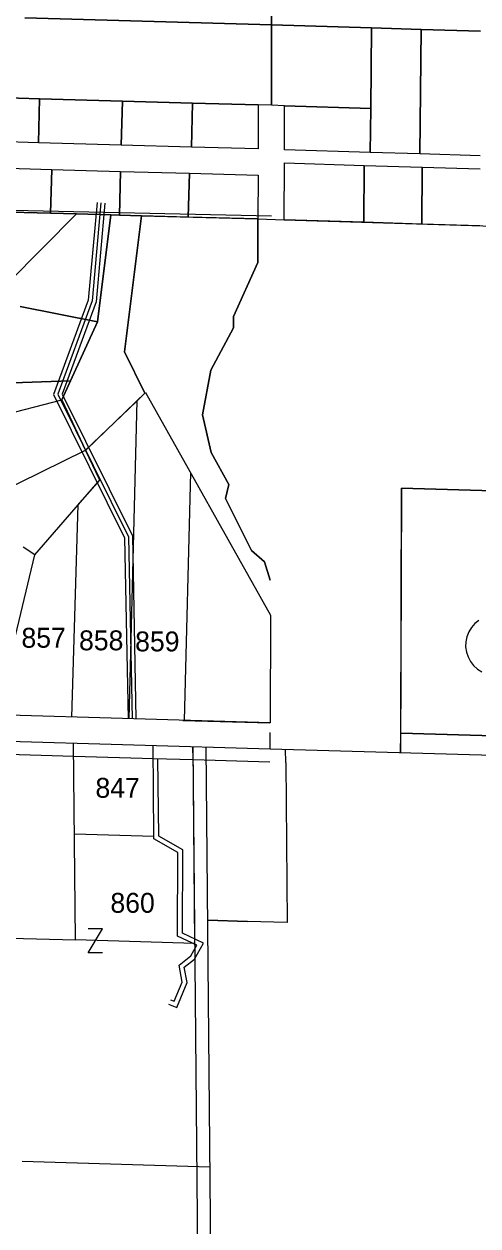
# Model space of a CAD drawing. Extents: x 582596 to 627039, y 145946 to 197316.
# Drawn here: x 619859 to 621001, y 163403 to 166425 of the extents above; entities that cross this region are included whole.
import ezdxf

# ---------------------------------------------------------------- set-up
doc = ezdxf.new("R2010")
doc.units = 0
for name, color, linetype in [('Defpoints 2', 7, 'Continuous'), ('E_RW_EasementUtility', 7, 'Continuous'), ('E_RW_Existing', 7, 'Continuous'), ('E_RW_SixteenthLine', 7, 'Continuous'), ('P_RW_MinorLotLine', 7, 'Continuous'), ('P_RW_PropertyConnector', 7, 'Continuous'), ('P_RW_PropertyLine', 7, 'Continuous'), ('P_RW_SectionLine', 7, 'Continuous')]:
    doc.layers.add(name, color=color, linetype=linetype)

msp = doc.modelspace()

# ---------------------------------------------------------------- linework, layer by layer
at = {"layer": 'E_RW_EasementUtility'}
msp.add_line((620317, 164607.9), (620340.4, 162042.5), dxfattribs=at)
for points in [[(620043.1, 165976.9), (620021, 165731.2), (619933.5, 165493.8), (620112.5, 165133.7), (620121, 164678.5)], [(620053, 165976), (620030.8, 165729), (619944.4, 165494.4), (620122.4, 165136.2), (620131, 164678.3)], [(620063, 165975.1), (620040.6, 165726.7), (619955.2, 165495), (620132.4, 165138.6), (620141, 164678)], [(620223.1, 163961.1), (620243.4, 163952.6), (620269.6, 164015.4), (620262.3, 164054), (620287.9, 164074.2), (620310.6, 164114.4), (620257.7, 164139.6), (620258.6, 164349.4), (620198.1, 164383.6), (620196.3, 164578.3)], [(620227.7, 163972.1), (620236.9, 163968.3), (620257.2, 164016.7), (620249.2, 164058.9), (620278.6, 164082.2), (620293.9, 164109.1), (620245.7, 164132.1), (620246.6, 164342.4), (620186.2, 164376.5), (620186.1, 164383.7)]]:
    msp.add_lwpolyline(points, dxfattribs=at)
at = {"layer": 'E_RW_Existing'}
for p, q in [((619575.4, 164596.3), (619984.8, 164584.4)), ((619984.8, 164584.4), (620184.7, 164578.7)), ((620284.6, 164575.8), (620477.6, 164570.2))]:
    msp.add_line(p, q, dxfattribs=at)
at = {"layer": 'E_RW_SixteenthLine'}
msp.add_line((617844.3, 166000.7), (620481.9, 165942.8), dxfattribs=at)
at = {"layer": 'P_RW_MinorLotLine'}
msp.add_line((620288.5, 164113.8), (619988.6, 164122.5), dxfattribs=at)
at = {"layer": 'P_RW_PropertyConnector'}
for p, q in [((620020.8, 164090.3), (620056.5, 164150.2)), ((620056.5, 164150.2), (620020.9, 164150.2)), ((620038.7, 164120.2), (620038.7, 164120.2)), ((620056.5, 164090.3), (620020.8, 164090.3))]:
    msp.add_line(p, q, dxfattribs=at)
at = {"layer": 'P_RW_PropertyLine'}
for p, q in [((620483.6, 167042.3), (620482, 166423.4)), ((620482, 166423.4), (620483.6, 167042.3)), ((619861.4, 166440.5), (620482, 166423.3)), ((620482, 166423.3), (619861.4, 166440.5)), ((620482, 166423.3), (620481.5, 166221.1)), ((620481.5, 166221.1), (620482, 166423.3)), ((620482, 166423.4), (620482, 166423.3)), ((620733.3, 166415.5), (620482, 166423.4)), ((620482, 166423.3), (620482, 166423.4)), ((620482, 166423.4), (620733.3, 166415.5)), ((620733.3, 166415.5), (620731.3, 166213.3)), ((620731.3, 166213.3), (620733.3, 166415.5)), ((620858.3, 166411.6), (620733.3, 166415.5)), ((620733.3, 166415.5), (620858.3, 166411.6)), ((620858.3, 166411.6), (620855.1, 166098.7)), ((620855.1, 166098.7), (620858.3, 166411.6)), ((621007.6, 166407), (620858.3, 166411.6)), ((620858.3, 166411.6), (621007.6, 166407)), ((619743.6, 166241.6), (619898.6, 166237.3)), ((619898.6, 166237.3), (619743.6, 166241.6)), ((619898.6, 166237.3), (619895.5, 166126.6)), ((619895.5, 166126.6), (619898.6, 166237.3)), ((619898.6, 166237.3), (620107.1, 166231.5)), ((620107.1, 166231.5), (619898.6, 166237.3)), ((620104.1, 166120.9), (620107.1, 166231.5)), ((620107.1, 166231.5), (620104.1, 166120.9)), ((620107.1, 166231.5), (620283.4, 166226.6)), ((620283.4, 166226.6), (620107.1, 166231.5)), ((620283.4, 166226.6), (620280.4, 166116)), ((620280.4, 166116), (620283.4, 166226.6)), ((620283.4, 166226.6), (620448.5, 166222)), ((620448.5, 166222), (620283.4, 166226.6)), ((620448.5, 166222), (620448.2, 166111.3)), ((620481.5, 166221.1), (620448.5, 166222)), ((620514.5, 166220), (620481.5, 166221.1)), ((620514.2, 166109.3), (620514.5, 166220)), ((620731.3, 166213.3), (620514.5, 166220)), ((620514.5, 166220), (620731.3, 166213.3)), ((620731.3, 166213.3), (620730.1, 166102.6)), ((620730.1, 166102.6), (620731.3, 166213.3)), ((619895.5, 166126.6), (619740.5, 166131)), ((620104.1, 166120.9), (619895.5, 166126.6)), ((620280.4, 166116), (620104.1, 166120.9)), ((620448.2, 166111.3), (620280.4, 166116)), ((620730.1, 166102.6), (620514.2, 166109.3)), ((620855.1, 166098.7), (620730.1, 166102.6)), ((621006.5, 166094), (620855.1, 166098.7)), ((619756.6, 166064.5), (619929.4, 166059.7)), ((619929.4, 166059.7), (619926.3, 165949.7)), ((619926.3, 165949.7), (619929.4, 166059.7)), ((619929.4, 166059.7), (620102.2, 166054.9)), ((620102.2, 166054.9), (620099.2, 165944.9)), ((620099.2, 165944.9), (620102.2, 166054.9)), ((620102.2, 166054.9), (620275.4, 166050.1)), ((620513.8, 165933.3), (620514.1, 166076.3)), ((620514.1, 166076.3), (620714.5, 166070)), ((620714.5, 166070), (620714, 165927.1)), ((620714, 165927.1), (620714.5, 166070)), ((620714.5, 166070), (620860.5, 166065.5)), ((620860.5, 166065.5), (620859.9, 165922.5)), ((620859.9, 165922.5), (620860.5, 166065.5)), ((620860.5, 166065.5), (621006.4, 166060.9)), ((620275.4, 166050.1), (620272.3, 165940.1)), ((620272.3, 165940.1), (620275.4, 166050.1)), ((620275.4, 166050.1), (620448.1, 166045.3)), ((620448.1, 166045.3), (620447.8, 165935.2)), ((619926.3, 165949.7), (619753.5, 165954.5)), ((619753.5, 165954.5), (619926.3, 165949.7)), ((619820.5, 165775.4), (619991.2, 165947.9)), ((619991.2, 165947.9), (619820.5, 165775.4)), ((619991.2, 165947.9), (619926.3, 165949.7)), ((619926.3, 165949.7), (619991.2, 165947.9)), ((620077.9, 165945.5), (619991.2, 165947.9)), ((619991.2, 165947.9), (620077.9, 165945.5)), ((620077.9, 165945.5), (620044.1, 165676.2)), ((620044.1, 165676.2), (620077.9, 165945.5)), ((620099.2, 165944.9), (620077.9, 165945.5)), ((620077.9, 165945.5), (620099.2, 165944.9)), ((620155, 165943.4), (620099.2, 165944.9)), ((620099.2, 165944.9), (620155, 165943.4)), ((620112.2, 165601.2), (620155, 165943.4)), ((620155, 165943.4), (620112.2, 165601.2)), ((620155, 165943.4), (620447.8, 165935.2)), ((620272.3, 165940.1), (620155, 165943.4)), ((620447.8, 165935.2), (620272.3, 165940.1)), ((620447.8, 165935.2), (620447.5, 165826.1)), ((620447.5, 165826.1), (620447.8, 165935.2)), ((620447.8, 165935.2), (620513.8, 165933.3)), ((620714, 165927.1), (620513.8, 165933.3)), ((620513.8, 165933.3), (621140.8, 165913.7)), ((620859.9, 165922.5), (620714, 165927.1)), ((621005.9, 165918), (620859.9, 165922.5)), ((620447.5, 165826.1), (620386.2, 165690.3)), ((620386.2, 165690.3), (620447.5, 165826.1)), ((619849.4, 165715.3), (620044.1, 165676.2)), ((620044.1, 165676.2), (619849.4, 165715.3)), ((620044.1, 165676.2), (619976.2, 165528)), ((619976.2, 165528), (620044.1, 165676.2)), ((620386.1, 165661.2), (620329, 165554.7)), ((620329, 165554.7), (620386.1, 165661.2)), ((620386.2, 165690.3), (620386.1, 165661.2)), ((620386.1, 165661.2), (620386.2, 165690.3)), ((620163.6, 165497.3), (620112.2, 165601.2)), ((620112.2, 165601.2), (620163.6, 165497.3)), ((620329, 165554.7), (620308.5, 165443)), ((620308.5, 165443), (620329, 165554.7)), ((619976.2, 165528), (619807, 165522.5)), ((619807, 165522.5), (619976.2, 165528)), ((619954.6, 165480.7), (619976.2, 165528)), ((619976.2, 165528), (619954.6, 165480.7)), ((619669.6, 165407), (619954.6, 165480.7)), ((619954.6, 165480.7), (620014.3, 165353.9)), ((620014.3, 165353.9), (619954.6, 165480.7)), ((620015.6, 165355.1), (620164.9, 165498.6)), ((620141.9, 165476.5), (620163.6, 165497.3)), ((620163.6, 165497.3), (620141.9, 165476.5)), ((620164.9, 165498.6), (620479.5, 164939.2)), ((620014.3, 165353.9), (620141.9, 165476.5)), ((620141.9, 165476.5), (620014.3, 165353.9)), ((620143.1, 165477.7), (620122.9, 164678.5)), ((620308.5, 165443), (620330.3, 165348)), ((620330.3, 165348), (620308.5, 165443)), ((619776.8, 165236.9), (620014.3, 165353.9)), ((620049.7, 165278.8), (620014.3, 165353.9)), ((620014.3, 165353.9), (620049.7, 165278.8)), ((620330.3, 165348), (620374.4, 165267.7)), ((620374.4, 165267.7), (620330.3, 165348)), ((619886.6, 165090.9), (620050.9, 165280)), ((619994.3, 165215), (620049.7, 165278.8)), ((620278, 165297.5), (620262.2, 164674.5)), ((620374.4, 165267.7), (620366.4, 165232.6)), ((620366.4, 165232.6), (620374.4, 165267.7)), ((620808.9, 165258.2), (620806.5, 164592.4)), ((620806.7, 164642.4), (620808.9, 165258.2)), ((621138.8, 165248.3), (620808.9, 165258.2)), ((620808.9, 165258.2), (621138.8, 165248.3)), ((619980.1, 164682.6), (619995.5, 165216.3)), ((620366.4, 165232.6), (620431.7, 165101.7)), ((620431.7, 165101.7), (620366.4, 165232.6)), ((619837.8, 164886.7), (619886.6, 165090.9)), ((619886.6, 165090.9), (619857.1, 165109.8)), ((620431.7, 165101.7), (620464.5, 165073.3)), ((620464.5, 165073.3), (620431.7, 165101.7)), ((620464.5, 165073.3), (620478.1, 165026.9)), ((620478.1, 165026.9), (620464.5, 165073.3)), ((620479.5, 164939.2), (620478.8, 164668.2)), ((620984.6, 164908), (620977.8, 164897)), ((620993.1, 164917.8), (620984.6, 164908)), ((621003.3, 164925.9), (620993.1, 164917.8)), ((620973, 164884.9), (620970.4, 164872.2)), ((620977.8, 164897), (620973, 164884.9)), ((620970.4, 164872.2), (620970, 164859.2)), ((620970, 164859.2), (620971.9, 164846.3)), ((620971.9, 164846.3), (620976, 164834)), ((620976, 164834), (620982.1, 164822.6)), ((620982.1, 164822.6), (620990.1, 164812.3)), ((620990.1, 164812.3), (620999.7, 164803.6)), ((620999.7, 164803.6), (621010.7, 164796.8)), ((620478.8, 164668.2), (619715.2, 164690.3)), ((620258.8, 164674.6), (620477.6, 164668.2)), ((620806.5, 164592.4), (620806.7, 164642.4)), ((621138.3, 164632.7), (620806.7, 164642.4)), ((620806.7, 164642.4), (621138.3, 164632.7)), ((619988.6, 164122.5), (619984.1, 164617.5)), ((620186.1, 164383.7), (620184, 164611.7)), ((620284, 164608.8), (620307.5, 162043.5)), ((620284, 164608.8), (620288.5, 164113.8)), ((620284.7, 164575.5), (620284.3, 164608.8)), ((620184.3, 164578.7), (620285.1, 164575.8)), ((620517.6, 164568.7), (620517.2, 164602.1)), ((620517.6, 164568.7), (620521.2, 164166.2)), ((619986.2, 164389.5), (620186.1, 164383.7)), ((620421.3, 164169.1), (620321.3, 164171.9)), ((620321.3, 164171.9), (620421.3, 164169.1)), ((620521.2, 164166.2), (620421.3, 164169.1)), ((619579.3, 164134.3), (619988.6, 164122.5)), ((620326.9, 163551.5), (619854.6, 163565.2))]:
    msp.add_line(p, q, dxfattribs=at)
at = {"layer": 'P_RW_SectionLine'}
for p, q in [((617840.9, 164679.4), (620478.6, 164603.2)), ((620478.6, 164603.2), (620478.6, 164644.4)), ((620317, 164607.9), (620340.4, 162042.5)), ((620478.6, 164603.2), (623115.6, 164526.5))]:
    msp.add_line(p, q, dxfattribs=at)

# ---------------------------------------------------------------- texts
at = {"layer": 'Defpoints 2'}
for s, p in [('857', (619853, 164857.2)), ('858', (619997.8, 164850.7)), ('859', (620138.9, 164848)), ('847', (620039.1, 164480)), ('860', (620076.7, 164190.8))]:
    msp.add_text(s, height=50, dxfattribs=at).set_placement(p)

doc.saveas('drawing.dxf')
